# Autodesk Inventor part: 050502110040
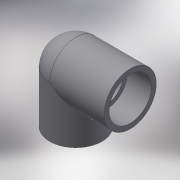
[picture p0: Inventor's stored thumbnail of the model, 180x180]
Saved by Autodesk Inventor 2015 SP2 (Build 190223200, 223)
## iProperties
Created: 2017-10
Part Number: 050502110040
Material: Generic
Description: PLASSON 90° ELBOW THR-CEM PVC 110-4"
Document SubType Name: Modeling
Designer: KIM
Density: 1 g/cm^3
Appearance: Default
Author: KIM
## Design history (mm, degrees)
derived "050502.ipt"
  workaxis "Work Axis3"
feature "Solid1::050502.ipt"
tag "TaggingFeature1"
workaxis "Work Axis2"
body "Solid1"
other parameters: "d1" = 132, "d3" = 118, "d4" = 132, "d6" = 90 deg, "d7" = 110.072, "d9" = 0, "d11" = 61, "d12" = 0, "d14" = 88.0576, "d16" = 55.036, "d17" = 0, "d18" = 0, "G_" = 110.072, "E_" = 132, "l_" = 61, "Z_" = 57, "H_" = 186
